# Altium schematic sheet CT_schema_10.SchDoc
size 274 x 160 mm
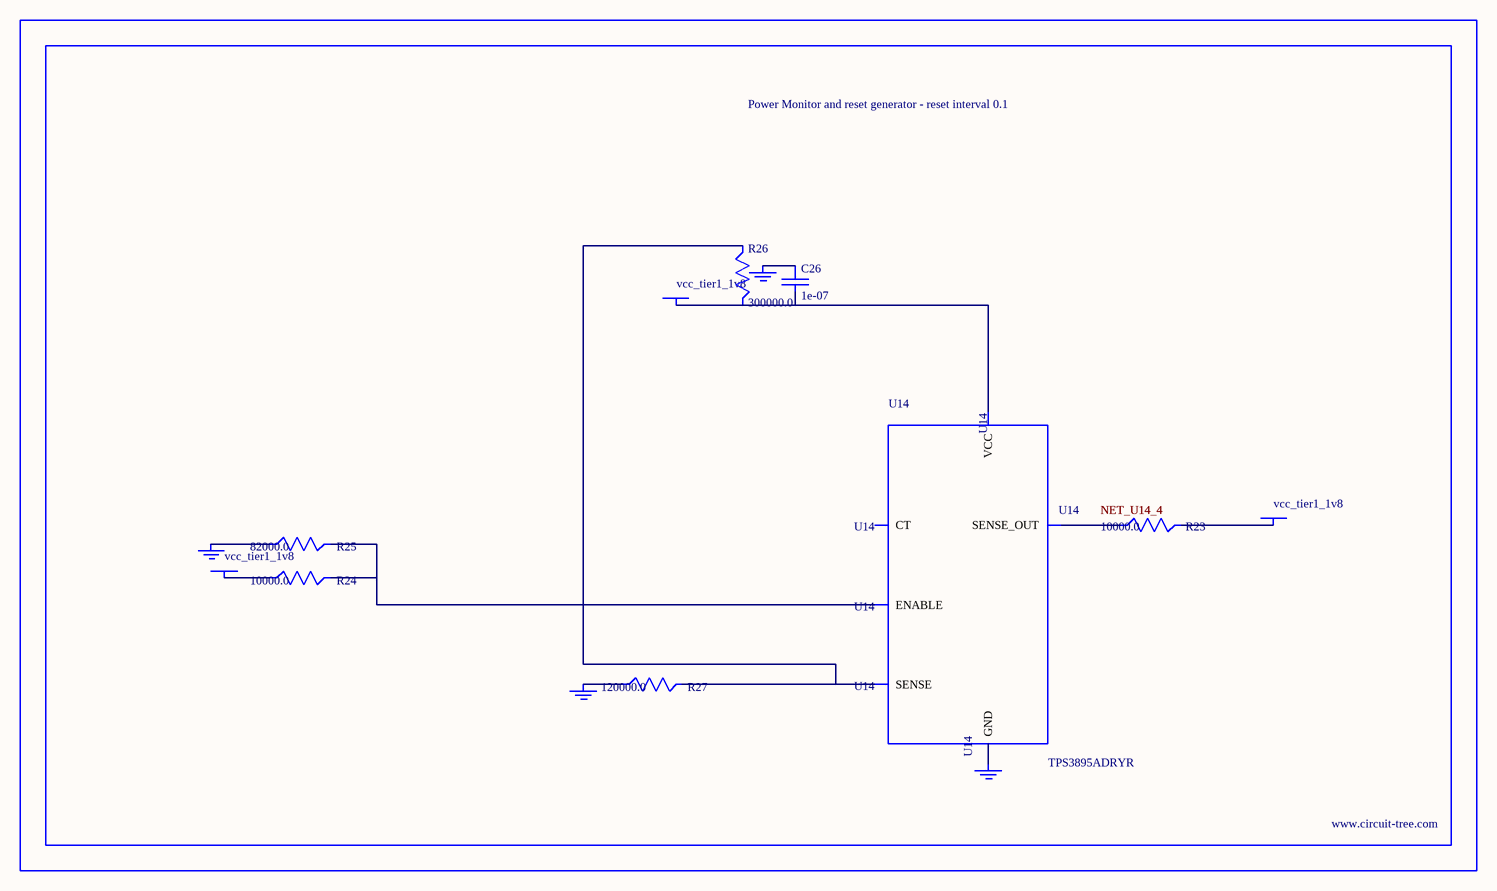
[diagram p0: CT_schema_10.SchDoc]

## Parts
BORDER9  (no value)
C26  1e-07  [C0402]
GND_INSTANCE_9_0  (no value)
GND_INSTANCE_9_1  (no value)
GND_INSTANCE_9_2  (no value)
GND_INSTANCE_9_3  (no value)
POWER_INSTANCE_9_0  vcc_tier1_1v8
POWER_INSTANCE_9_1  vcc_tier1_1v8
POWER_INSTANCE_9_2  vcc_tier1_1v8
R23  10000.0  [R0603]
R24  10000.0  [R0603]
R25  82000.0  [R0603]
R26  300000.0  [R0603]
R27  120000.0  [R0603]
U14  TPS3895ADRYR  [SON-6]

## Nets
NetC26_1: C26.1 GND_INSTANCE_9_2.0(GND)
NetC26_2: C26.2 POWER_INSTANCE_9_2.0(PWR) R26.2 U14.6(VCC)
NetGND_INSTANCE_9_0_0: GND_INSTANCE_9_0.0(GND) R25.1
NetGND_INSTANCE_9_1_0: GND_INSTANCE_9_1.0(GND) R27.1
NetGND_INSTANCE_9_3_0: GND_INSTANCE_9_3.0(GND) U14.2(GND)
NetPOWER_INSTANCE_9_0_0: POWER_INSTANCE_9_0.0(PWR) R24.1
NetPOWER_INSTANCE_9_1_0: POWER_INSTANCE_9_1.0(PWR) R23.2
NetR23_1: R23.1 U14.4(SENSE_OUT)
NetR24_2: R24.2 R25.2 U14.1(ENABLE)
NetR26_1: R26.1 R27.2 U14.3(SENSE)

Not connected (* = marked no-connect by the designer): U14 5(CT)

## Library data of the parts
BORDER9 = BORDER_PAGE9
C26 = C0402C104K3RACTU
GND_INSTANCE_9_0-GND_INSTANCE_9_3 = GND
POWER_INSTANCE_9_0-POWER_INSTANCE_9_2 = PWR
R23 R24 = RC0603JR-0710KL
R25 = RC0603JR-0782KL
R26 = RC0603JR-07300KL
R27 = RC0603JR-07120KL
